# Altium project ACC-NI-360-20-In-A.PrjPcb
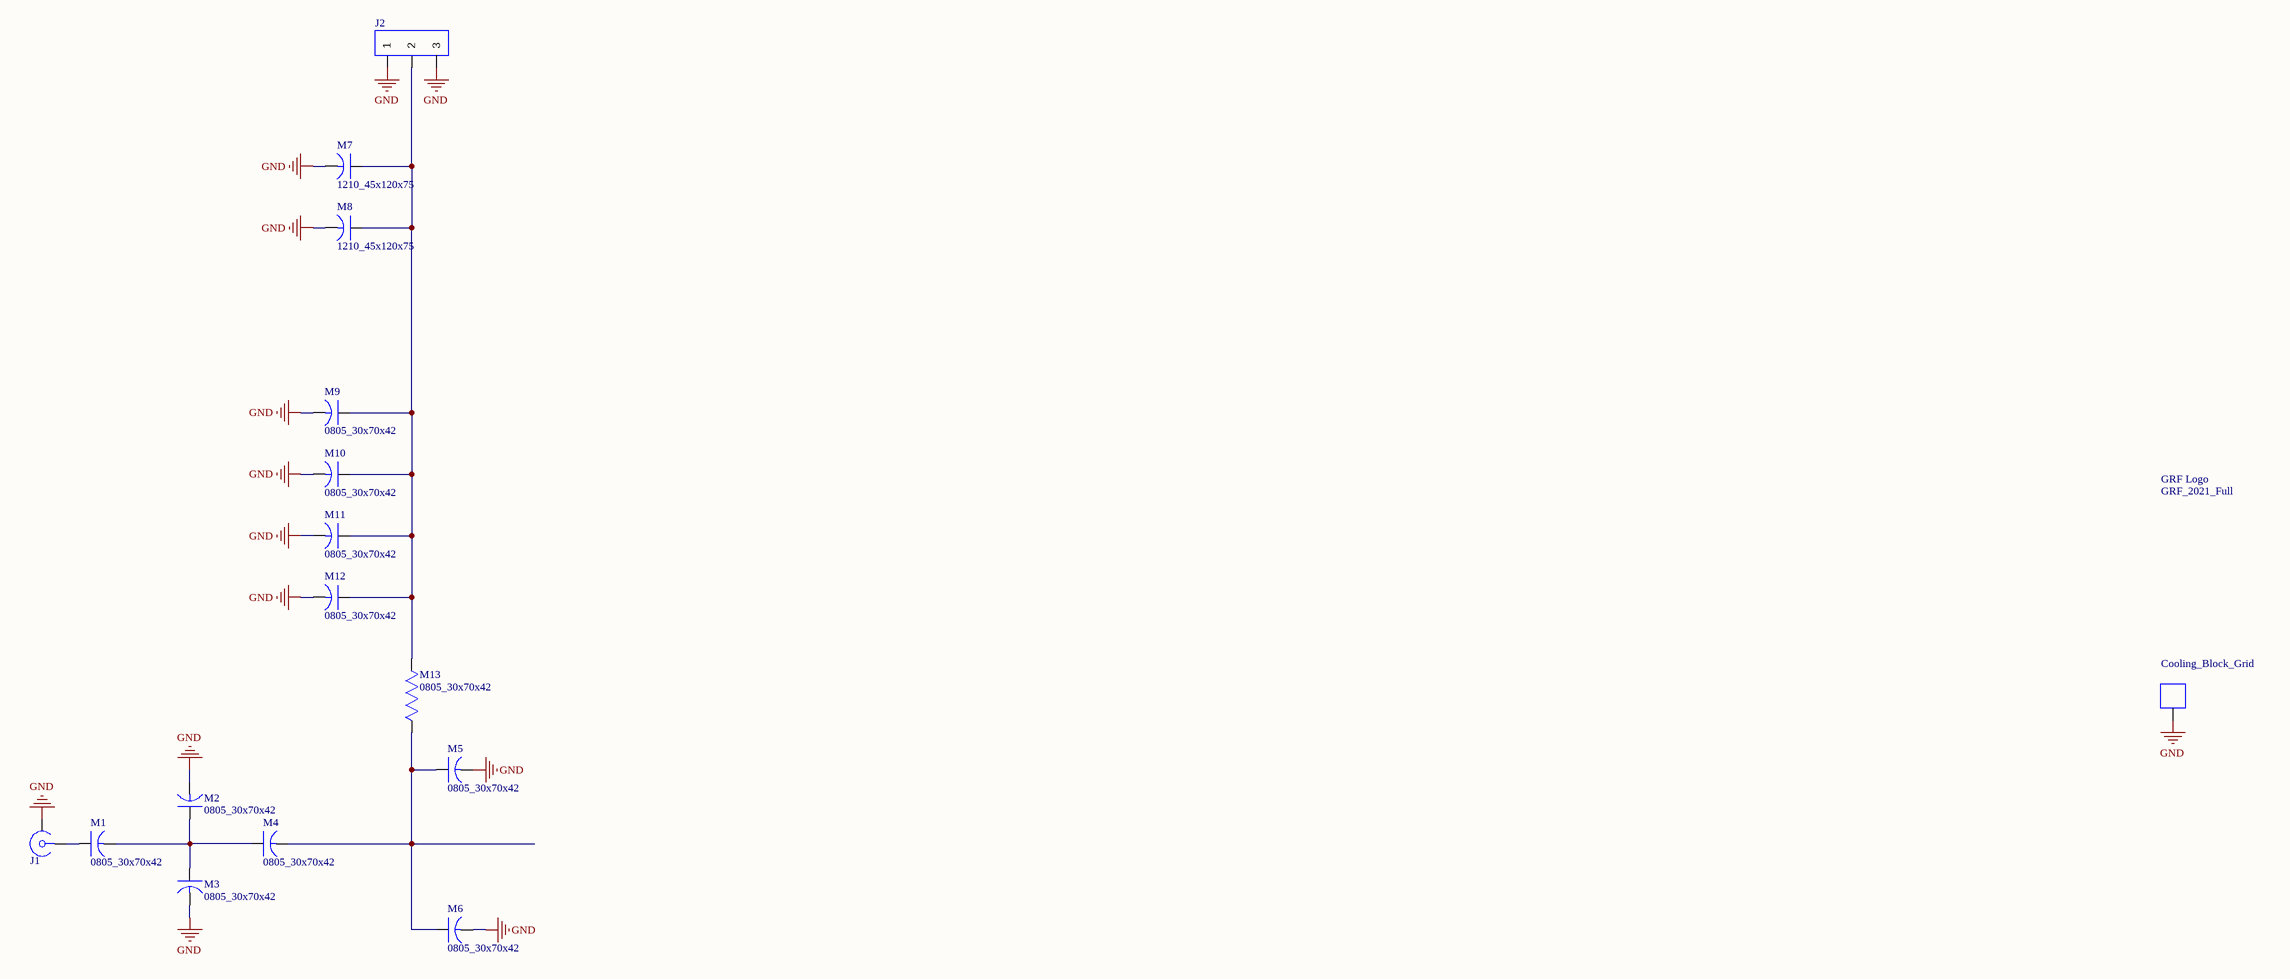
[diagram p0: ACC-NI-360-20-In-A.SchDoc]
Description: Layout updates; Modified From: DFN6-15-34-A (Eagle)
1 sheet, 17 parts. Net scope: global (net labels, ports and power ports of the same name join across sheets).
Board file: ACC-NI-360-20-In-A.PcbDoc

## Sheet ACC-NI-360-20-In-A.SchDoc
size 609 x 419 mm; Revision: A; SheetNumber: 1; SheetTotal: 1

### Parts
H1  Cooling_Block_Grid  [Cooling_Block_Grid]
J1  SMA Panel Mount_RevB  [SMA Panel Mount_RevB]  (value not drawn)
J2  Header_H_3-Pin_100mil  [Header_H_3-Pin_100mil]  (value not drawn)
Logo1  GRF_2021_Full  [GRF_2021_Full]
M1  0805_30x70x42  [0805_30x70x42]
M2  0805_30x70x42  [0805_30x70x42]
M3  0805_30x70x42  [0805_30x70x42]
M4  0805_30x70x42  [0805_30x70x42]
M5  0805_30x70x42  [0805_30x70x42]
M6  0805_30x70x42  [0805_30x70x42]
M7  1210_45x120x75  [1210_45x120x75]
M8  1210_45x120x75  [1210_45x120x75]
M9  0805_30x70x42  [0805_30x70x42]
M10  0805_30x70x42  [0805_30x70x42]
M11  0805_30x70x42  [0805_30x70x42]
M12  0805_30x70x42  [0805_30x70x42]
M13  0805_30x70x42  [0805_30x70x42]

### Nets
GND: H1.1 J1.2 J2.1 J2.3 M2.1 M3.1 M5.1 M6.1 M7.1 M8.1 M9.1 M10.1 M11.1 M12.1
NetJ1_1: J1.1 M1.2
NetJ2_2: J2.2 M7.2 M8.2 M9.2 M10.2 M11.2 M12.2 M13.2
NetM1_1: M1.1 M2.2 M3.2 M4.2
NetM4_1: M4.1 M5.2 M6.2 M13.1

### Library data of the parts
H1 = Mounting Holes
J1 = RF_Conn
J2 = Header_3-Pin: Header 3-Pin
Logo1 = GRF_Logo: =CurrentFootprint
M1-M12 = Capacitor
M13 = Resistor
